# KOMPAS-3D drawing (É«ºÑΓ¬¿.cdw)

Referenced files: Розетки.cdw
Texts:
  Microsoft
  Текст на чертеже
  Размерные надписи
  Шероховатость
  Линия-выноска #1
  Линия-выноска #2
  Линия-выноска #3
  Отклонения формы и база
  Заголовок таблицы
  Ячейка таблицы
  Стрелка вида
  Обозначение изменения
  Фигурная скобка
  Номер узла
  Марка координационной оси
  VRCB
  Выносная надпись
  Обозначение узла
  Марка/позиционное обозначение с линией-выноской
  Марка/позиционное обозначение на линии
  Марка/позиционное обозначение без линии-выноски
  РЩ1
  РЩ2
  РЩ3
  гр.24
  гр.25
  гр.26
  гр.27
  гр.28
  гр.29
  гр.30
  гр.53
  гр.54
  гр.55
  гр.40
  гр.41
  гр.56
  гр.57
  гр.51
  гр.52
  РЩ4
  РЩ5
  РЩ6
  РЩ7
  гр.7
  гр.8
  гр.9
  гр.15а
  гр.15б
  гр.15в
  гр.58
  гр.60
  гр.59
Dimensions and other numbers on the sheet: 7; 4; 1:1; 0; 1; 2; 3; 5; 6; 8; 9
